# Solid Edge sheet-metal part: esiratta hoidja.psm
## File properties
Title: esiratta hoidja
Author: Stella-Marii
Template: Iso Metric Sheet Metal.psm
Last saved by: Stella-Marii
Revision: 9
Application: Solid Edge
Density: 7833,000 kg/m^3
Accuracy: 0,990
Material Thickness: 1,00 mm
Bend Radius: 1,00 mm
Relief Width: 1,00 mm
Relief Length: 0,00 mm
Neutral Factor: 0,330
Minimum Arc Length: 0,10 mm
Deviational Tolerance: 0,10 mm
Username: Stella-Marii
Document Number: 14
Material: Steel, structural
Face Style: Steel
Fill Style: ANSI32(Steel)
Virtual Style: Brushed steel
Grouping: Metals\Steel
LibraryName: Materials
Coef. of Thermal Exp: 1.3e-05
Thermal Conductivity: 32.0
Specific Heat: 481.0
Modulus of Elasticity: 199947953000.0
Poisson's Ratio: 0.29
Yield Stress: 262000766.0
Ultimate Stress: 358527364.0
Elongation: 0.0
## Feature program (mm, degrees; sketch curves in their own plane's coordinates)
base contour flange "ContourFlange_1"
sketch for "ExtrudedCutout_1" plane through (0, 0, 0) normal (0, -1, 0) x-axis (1, 0, 0)
  line (7.7891, -0.2) -> (25, 97.408)
extrude "ExtrudedCutout_1" cut
break corner "BreakCorner_1"  SetBackValue1 = 8 mm
break corner "BreakCorner_2"  SetBackValue1 = 8 mm
mirror "unnamed Mirror 1" of "BreakCorner_2", "BreakCorner_1", "ExtrudedCutout_1"
pattern "unnamed Pattern 1"
sheet metal cutout "SheetMetalCutout_1"
sketch for "ExtrudedCutout_2" plane through (0, 0, 0) normal (0, -1, 0) x-axis (1, 0, 0)
  circle centre (0, 11) radius 6.5
extrude "ExtrudedCutout_2" cut
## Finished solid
Body 1: solid body, 42 faces, 120 edges, 80 vertices.
  Faces by surface: plane 24, cylinder 18
  Edges by curve: line 80, circle 28, ellipse 12
Bounding box of the edges (mm): 50.000 x 91.815 x 133.571, from (-25, -45.9074, 0.0495) to (25, 45.9074, 133.6206).
Cylindrical faces by radius (mm): R1 x6, R2 x6, R6.5 x2, R8 x4
Planar faces by outward normal: +x 3, +y 2, +z 1, -x 3, -y 2, -z 1, oblique 12
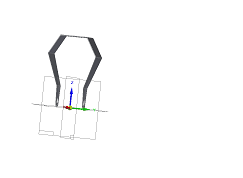
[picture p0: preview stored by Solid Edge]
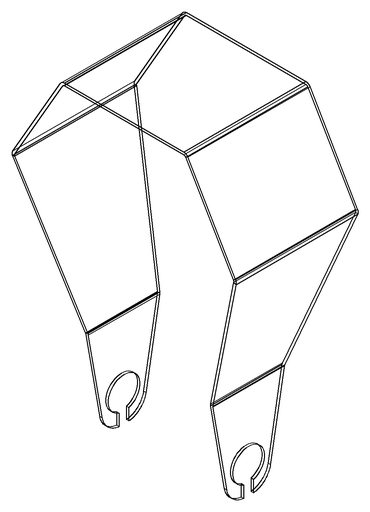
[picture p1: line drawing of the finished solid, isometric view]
